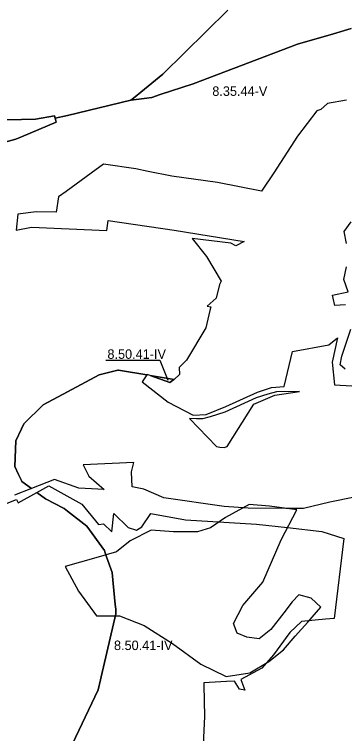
# Model space of a CAD drawing. Extents: x -547623 to -533936, y -1096714 to -1086523.
# Drawn here: x -544086 to -543738, y -1093125 to -1092367 of the extents above; entities that cross this region are included whole.
import ezdxf

# ---------------------------------------------------------------- set-up
doc = ezdxf.new("R2010")
doc.units = 0
for name, color, linetype in [('Vrstva 27', 7, 'Continuous'), ('Vrstva 28', 7, 'Continuous'), ('Vrstva 29', 7, 'Continuous')]:
    doc.layers.add(name, color=color, linetype=linetype)

msp = doc.modelspace()

# ---------------------------------------------------------------- linework, layer by layer
at = {"layer": 'Vrstva 27'}
msp.add_lwpolyline([(-543989.91, -1092731.46), (-543933.08, -1092731.46), (-543924.81, -1092752.45)], dxfattribs=at)
at = {"layer": 'Vrstva 28'}
for p, q in [((-543861.5, -1092362.5), (-543930, -1092430)), ((-543930, -1092430), (-543861.5, -1092362.5)), ((-543750, -1092387.4), (-543731.5, -1092382)), ((-543731.5, -1092382), (-543750, -1092387.4)), ((-543788, -1092398.5), (-543750, -1092387.4)), ((-543750, -1092387.4), (-543788, -1092398.5)), ((-543898, -1092440), (-543788, -1092398.5)), ((-543788, -1092398.5), (-543898, -1092440)), ((-543930, -1092430), (-543953.08, -1092448.94)), ((-543953.08, -1092448.94), (-543930, -1092430)), ((-543932.59, -1092451.53), (-543898, -1092440)), ((-543898, -1092440), (-543932.59, -1092451.53)), ((-543953.08, -1092448.94), (-543959.09, -1092453.88)), ((-543959.09, -1092453.88), (-543953.08, -1092448.94)), ((-543941.5, -1092454.5), (-543932.59, -1092451.53)), ((-543932.59, -1092451.53), (-543941.5, -1092454.5)), ((-544030.47, -1092473.41), (-543963.5, -1092457.5)), ((-543963.5, -1092457.5), (-544030.47, -1092473.41)), ((-543959.09, -1092453.88), (-543963.5, -1092457.5)), ((-543963.5, -1092457.5), (-543959.09, -1092453.88)), ((-543963.5, -1092457.5), (-543946.91, -1092455.24)), ((-543946.91, -1092455.24), (-543963.5, -1092457.5)), ((-543946.91, -1092455.24), (-543941.5, -1092454.5)), ((-543941.5, -1092454.5), (-543946.91, -1092455.24)), ((-544064, -1092477.5), (-544044, -1092474)), ((-544044, -1092474), (-544064, -1092477.5)), ((-544044, -1092474), (-544043.43, -1092476.48)), ((-544043.43, -1092476.48), (-544044, -1092474)), ((-544043.43, -1092476.48), (-544030.47, -1092473.41)), ((-544030.47, -1092473.41), (-544043.43, -1092476.48)), ((-544127.5, -1092478.5), (-544079.02, -1092477.74)), ((-544079.02, -1092477.74), (-544127.5, -1092478.5)), ((-544079.02, -1092477.74), (-544064, -1092477.5)), ((-544064, -1092477.5), (-544079.02, -1092477.74)), ((-544042.5, -1092480.5), (-544079.02, -1092495.97)), ((-544079.02, -1092495.97), (-544042.5, -1092480.5)), ((-544043.43, -1092476.48), (-544042.5, -1092480.5)), ((-544042.5, -1092480.5), (-544043.43, -1092476.48)), ((-544079.02, -1092495.97), (-544085, -1092498.5)), ((-544085, -1092498.5), (-544079.02, -1092495.97)), ((-544085, -1092498.5), (-544141.95, -1092513.82)), ((-544141.95, -1092513.82), (-544085, -1092498.5)), ((-543997, -1092747), (-544030.47, -1092764.87)), ((-544030.47, -1092764.87), (-543997, -1092747)), ((-543977.26, -1092742.18), (-543997, -1092747)), ((-543997, -1092747), (-543977.26, -1092742.18)), ((-543976.5, -1092742), (-543977.26, -1092742.18)), ((-543977.26, -1092742.18), (-543976.5, -1092742)), ((-543974.72, -1092742.3), (-543976.5, -1092742)), ((-543976.5, -1092742), (-543974.72, -1092742.3)), ((-543946.82, -1092746.99), (-543974.72, -1092742.3)), ((-543974.72, -1092742.3), (-543946.82, -1092746.99)), ((-543920.15, -1092751.47), (-543943.29, -1092747.58)), ((-543943.29, -1092747.58), (-543920.15, -1092751.47)), ((-543943.29, -1092747.58), (-543943.29, -1092747.58)), ((-543943.29, -1092747.58), (-543943.29, -1092747.58)), ((-543918.14, -1092751.81), (-543920.15, -1092751.47)), ((-543920.15, -1092751.47), (-543918.14, -1092751.81)), ((-543918.14, -1092751.81), (-543918.14, -1092751.81)), ((-543918.14, -1092751.81), (-543918.14, -1092751.81)), ((-544030.47, -1092764.87), (-544056, -1092778.5)), ((-544056, -1092778.5), (-544030.47, -1092764.87)), ((-544056, -1092778.5), (-544076.5, -1092798.5)), ((-544076.5, -1092798.5), (-544056, -1092778.5)), ((-544076.5, -1092798.5), (-544079.02, -1092803.85)), ((-544079.02, -1092803.85), (-544076.5, -1092798.5)), ((-544079.02, -1092803.85), (-544085, -1092816.5)), ((-544085, -1092816.5), (-544079.02, -1092803.85)), ((-544085, -1092816.5), (-544086, -1092843.5)), ((-544086, -1092843.5), (-544085, -1092816.5)), ((-544086, -1092843.5), (-544082.02, -1092851.99)), ((-544082.02, -1092851.99), (-544086, -1092843.5)), ((-544082.02, -1092851.99), (-544079.02, -1092858.38)), ((-544079.02, -1092858.38), (-544082.02, -1092851.99)), ((-544079.02, -1092858.38), (-544078.5, -1092859.5)), ((-544078.5, -1092859.5), (-544079.02, -1092858.38)), ((-544078.5, -1092859.5), (-544068.28, -1092866.86)), ((-544068.28, -1092866.86), (-544078.5, -1092859.5)), ((-544062.65, -1092870.91), (-544053.5, -1092877.5)), ((-544053.5, -1092877.5), (-544062.65, -1092870.91)), ((-544062.65, -1092870.91), (-544062.65, -1092870.91)), ((-544062.65, -1092870.91), (-544062.65, -1092870.91)), ((-544053.5, -1092877.5), (-544034, -1092888)), ((-544034, -1092888), (-544053.5, -1092877.5)), ((-544034, -1092888), (-544030.47, -1092890.72)), ((-544030.47, -1092890.72), (-544034, -1092888)), ((-544030.47, -1092890.72), (-544010, -1092906.5)), ((-544010, -1092906.5), (-544030.47, -1092890.72)), ((-544010, -1092906.5), (-543991.5, -1092932)), ((-543991.5, -1092932), (-544010, -1092906.5)), ((-543991.5, -1092932), (-543990.95, -1092933.62)), ((-543990.95, -1092933.62), (-543991.5, -1092932)), ((-543990.95, -1092933.62), (-543989.17, -1092938.83)), ((-543989.17, -1092938.83), (-543990.95, -1092933.62)), ((-543989.17, -1092938.83), (-543983.5, -1092955.5)), ((-543983.5, -1092955.5), (-543989.17, -1092938.83)), ((-543983.5, -1092955.5), (-543982.31, -1092966.97)), ((-543982.31, -1092966.97), (-543983.5, -1092955.5)), ((-543982.31, -1092966.97), (-543980.01, -1092989.1)), ((-543980.01, -1092989.1), (-543982.31, -1092966.97)), ((-543980.01, -1092989.1), (-543979.76, -1092991.46)), ((-543979.76, -1092991.46), (-543980.01, -1092989.1)), ((-543979.76, -1092991.46), (-543979.5, -1092994)), ((-543979.5, -1092994), (-543979.76, -1092991.46)), ((-543979.5, -1092994), (-543979.5, -1092999)), ((-543979.5, -1092999), (-543979.5, -1092994)), ((-543979.5, -1092999), (-543994.82, -1093065.25)), ((-543994.82, -1093065.25), (-543979.5, -1092999)), ((-543994.82, -1093065.25), (-543995.57, -1093068.47)), ((-543995.57, -1093068.47), (-543994.82, -1093065.25)), ((-543995.57, -1093068.47), (-543998, -1093079)), ((-543998, -1093079), (-543995.57, -1093068.47)), ((-543998, -1093079), (-544030.47, -1093147.12)), ((-544030.47, -1093147.12), (-543998, -1093079))]:
    msp.add_line(p, q, dxfattribs=at)
for points in [[(-543736.26, -1092457.38), (-543756.35, -1092461.06), (-543763.37, -1092467.31), (-543767.56, -1092468.8), (-543787.95, -1092495.31), (-543813, -1092534.03), (-543825.99, -1092553.16), (-543872.5, -1092544.02), (-543920.4, -1092537.48), (-543945.58, -1092532.47), (-543958.32, -1092529.92), (-543992.34, -1092524.7), (-544005.64, -1092534.41), (-544031.95, -1092553.63), (-544039.86, -1092559.41), (-544042.4, -1092575.41), (-544063.57, -1092575.13), (-544082.9, -1092577.5), (-544084.38, -1092594.31), (-544068.29, -1092591.27), (-543989.02, -1092594.93), (-543987.5, -1092584.22), (-543918.02, -1092594.55), (-543844.41, -1092606.47), (-543853, -1092610.9), (-543858.24, -1092608.28), (-543899.12, -1092603.26), (-543883.95, -1092622.06), (-543868.49, -1092648.24), (-543870.18, -1092651.79), (-543873.73, -1092666.2), (-543883.33, -1092674.42), (-543879.28, -1092675.24), (-543880.35, -1092679.08), (-543884.65, -1092697.43), (-543904.89, -1092731.48), (-543912.75, -1092739.22), (-543912.35, -1092746.73), (-543918.14, -1092751.81), (-543918.38, -1092752.02), (-543922.47, -1092755.01), (-543943.29, -1092747.58), (-543946.46, -1092746.45), (-543946.82, -1092746.99), (-543946.82, -1092746.99), (-543946.82, -1092746.99), (-543951.79, -1092754.39), (-543924.23, -1092775.6), (-543898.03, -1092789.34), (-543884.32, -1092788.85), (-543863.44, -1092780.47), (-543830.08, -1092765.34), (-543815.45, -1092760.25), (-543802.04, -1092759.3), (-543793.17, -1092722.29), (-543755.12, -1092715.47), (-543745.87, -1092708.11), (-543751.69, -1092733.73), (-543749.08, -1092757.6), (-543730.85, -1092758.45)], [(-544141.95, -1092513.82), (-544085, -1092498.5), (-544079.02, -1092495.97), (-544042.5, -1092480.5), (-544043.43, -1092476.48), (-544044, -1092474), (-544064, -1092477.5), (-544079.02, -1092477.74), (-544127.5, -1092478.5)], [(-543736.38, -1092608.66), (-543738.83, -1092595.74), (-543731.63, -1092585.8)], [(-543737.44, -1092673.13), (-543748.77, -1092673.75), (-543750.57, -1092666.13), (-543751.31, -1092662.9), (-543734.54, -1092659.62), (-543739.14, -1092646.56), (-543736.53, -1092633.08)], [(-543737.84, -1092740.87), (-543743.08, -1092736.25), (-543741.42, -1092727.31), (-543731.94, -1092698.78)], [(-543943.29, -1092747.58), (-543922.47, -1092755.01), (-543918.38, -1092752.02), (-543918.14, -1092751.81)], [(-543918.14, -1092751.81), (-543918.14, -1092751.81), (-543920.15, -1092751.47), (-543943.29, -1092747.58), (-543943.29, -1092747.58)], [(-543888.2, -1092793.25), (-543894.54, -1092793.37), (-543901.97, -1092792.92), (-543873.29, -1092822.47), (-543870.03, -1092823.2), (-543865.17, -1092823.44), (-543862.26, -1092822.55), (-543833.95, -1092777.85), (-543812.04, -1092768.31), (-543785.85, -1092764.59), (-543810.29, -1092765.03), (-543819.33, -1092767.2), (-543831.69, -1092771.28), (-543864.72, -1092786.3), (-543880.23, -1092791.37), (-543888.2, -1092793.25)], [(-543960.51, -1092839.2), (-544013.89, -1092841.78)], [(-544013.89, -1092841.78), (-544007.97, -1092853.76)], [(-543963.08, -1092849.09), (-543960.51, -1092839.2)], [(-543962.13, -1092865.08), (-543963.08, -1092849.09)], [(-544044.26, -1092857.41), (-544068.28, -1092866.86)], [(-544018.56, -1092866.5), (-544044.26, -1092857.41)], [(-544007.97, -1092853.76), (-543991.88, -1092867.93)], [(-544068.28, -1092866.86), (-544086.37, -1092873.97)], [(-544062.65, -1092870.91), (-544049.97, -1092863.87)], [(-544049.97, -1092863.87), (-544015.14, -1092883.38)], [(-543991.88, -1092867.93), (-544018.56, -1092866.5)], [(-543950.04, -1092867.58), (-543962.13, -1092865.08)], [(-543928.95, -1092876.77), (-543950.04, -1092867.58)], [(-544082.51, -1092881.95), (-544062.65, -1092870.91)], [(-543727.83, -1092876.02), (-543753.88, -1092881.02), (-543781.67, -1092887.9), (-543800.27, -1092887.79)], [(-544131.61, -1092897.15), (-544084.17, -1092878.53)], [(-544084.17, -1092878.53), (-544082.51, -1092881.95)], [(-544015.14, -1092883.38), (-543997.81, -1092904.71)], [(-543865.16, -1092885.7), (-543928.95, -1092876.77)], [(-543840.09, -1092887.56), (-543865.16, -1092885.7)], [(-543800.27, -1092887.79), (-543840.09, -1092887.56)], [(-543983.78, -1092912.37), (-543981.59, -1092893.18)], [(-543981.59, -1092893.18), (-543966.46, -1092907.72)], [(-543952.05, -1092907.25), (-543942.51, -1092893.19)], [(-543942.51, -1092893.19), (-543906.14, -1092899.79)], [(-543997.81, -1092904.71), (-543992.56, -1092903.93)], [(-543992.56, -1092903.93), (-543983.78, -1092912.37)], [(-543906.14, -1092899.79), (-543831.35, -1092904.42)], [(-543831.35, -1092904.42), (-543798.46, -1092908.05)], [(-543966.46, -1092907.72), (-543957.68, -1092910.8)], [(-543957.68, -1092910.8), (-543952.05, -1092907.25)], [(-543798.46, -1092908.05), (-543762.49, -1092912.02), (-543739.33, -1092919.43), (-543749.35, -1093003.78), (-543758.72, -1093004.7), (-543783.99, -1093006.95), (-543796.29, -1093018.61), (-543813.34, -1093042.3), (-543825.53, -1093056.17), (-543847.68, -1093068.03), (-543843.62, -1093079.48), (-543849.04, -1093078.42), (-543854.48, -1093069.76), (-543862.7, -1093070.23), (-543886.71, -1093071.6), (-543886.66, -1093073.94), (-543885.89, -1093107.07), (-543888.99, -1093166.48)]]:
    msp.add_lwpolyline(points, dxfattribs=at)
at = {"layer": 'Vrstva 29'}
msp.add_lwpolyline([(-543788.6, -1092889.32), (-543817.63, -1092885.52), (-543838.93, -1092883.75), (-543863.98, -1092897.21), (-543879.6, -1092908.25), (-543893.56, -1092912.55), (-543918.6, -1092912.46), (-543942.21, -1092910.72), (-543964.23, -1092921.92), (-543978.89, -1092933.56), (-544000.46, -1092939.94), (-544032.77, -1092949.13), (-544018.88, -1092975), (-543999.88, -1093000.85), (-543975.6, -1093000.87), (-543949.75, -1093011.26), (-543919.61, -1093030.24), (-543889.74, -1093052.01), (-543863.12, -1093065.03), (-543838.45, -1093060.99), (-543818.41, -1093049.1), (-543802.66, -1093036.79), (-543790.55, -1093022.35), (-543777.12, -1093007.52), (-543763.35, -1092991.7), (-543773.72, -1092982.53), (-543786.65, -1092978.74), (-543793.75, -1092986.24), (-543802.54, -1092997.94), (-543815.98, -1093015.58), (-543828.39, -1093025.13), (-543841.28, -1093023.65), (-543851.61, -1093019.34), (-543855.5, -1093009.25), (-543845.51, -1092990.26), (-543824.74, -1092965.39), (-543805.14, -1092920.72), (-543788.6, -1092889.32)], dxfattribs=at)

# ---------------------------------------------------------------- texts
at = {"layer": 'Vrstva 27'}
for s, p in [('8.35.44-V', (-543877.85, -1092452.86)), ('8.50.41-IV', (-543988.34, -1092730.08)), ('8.50.41-IV', (-543981.43, -1093037.09))]:
    msp.add_text(s, height=10, dxfattribs=at).set_placement(p)

doc.saveas('drawing.dxf')
